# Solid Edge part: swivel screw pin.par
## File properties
Author: Deepak Maini
Template: Normal.par
Last saved by: Robert a Rhodes jr
Revision: 4
Application: Solid Edge
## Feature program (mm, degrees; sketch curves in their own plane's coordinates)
sketch for "unnamed RevolvedProtrusion 1" plane through (0, 0, 0) normal (0, -1, 0) x-axis (1, 0, 0)
  line (0, 37.2096) -> (15, 37.2096)
  line (15, 37.2096) -> (15, 31.2096)
  line (15, 31.2096) -> (11, 31.2096)
  line (11, 31.2096) -> (11, 17.7744)
  line (11, 17.7744) -> (8, 17.7744)
  line (8, 17.7744) -> (8, 14.7744)
  line (8, 14.7744) -> (10, 14.7744)
  line (10, 14.7744) -> (10, -0.7904)
  line (10, -0.7904) -> (0, -0.7904)
  line (0, -0.7904) -> (0, 37.2096)
revolve "unnamed RevolvedProtrusion 1" add finite 360 deg
sketch for "unnamed Cutout 1" plane through (0, 0, 37.2096) normal (0, 0, 1) x-axis (0, 1, 0)
  line (-1.5, 15.984) -> (-1.5, -16.344)
  line (-1.5, -16.344) -> (1.5, -16.344)
  line (1.5, -16.344) -> (1.5, 15.984)
  line (1.5, 15.984) -> (-1.5, 15.984)
extrude "unnamed Cutout 1" cut finite 3.5 along -normal
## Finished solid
Body 1: solid body, 13 faces, 19 edges, 8 vertices.
  Faces by surface: plane 9, cylinder 4
  Edges by curve: circle 11, line 8
Bounding box of the edges (mm): 30.000 x 30.000 x 38.000, from (-15, -15, -0.7904) to (15, 15, 37.2096).
Cylindrical faces by radius (mm): R8 x1, R10 x1, R11 x1, R15 x1
Planar faces by outward normal: +y 1, +z 4, -y 1, -z 3
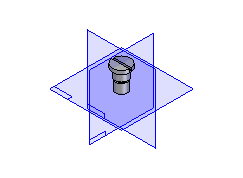
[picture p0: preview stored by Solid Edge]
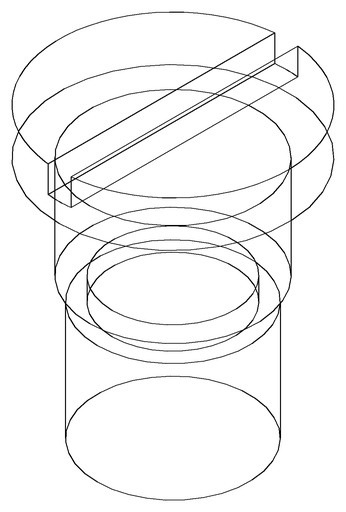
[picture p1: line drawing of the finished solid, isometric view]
